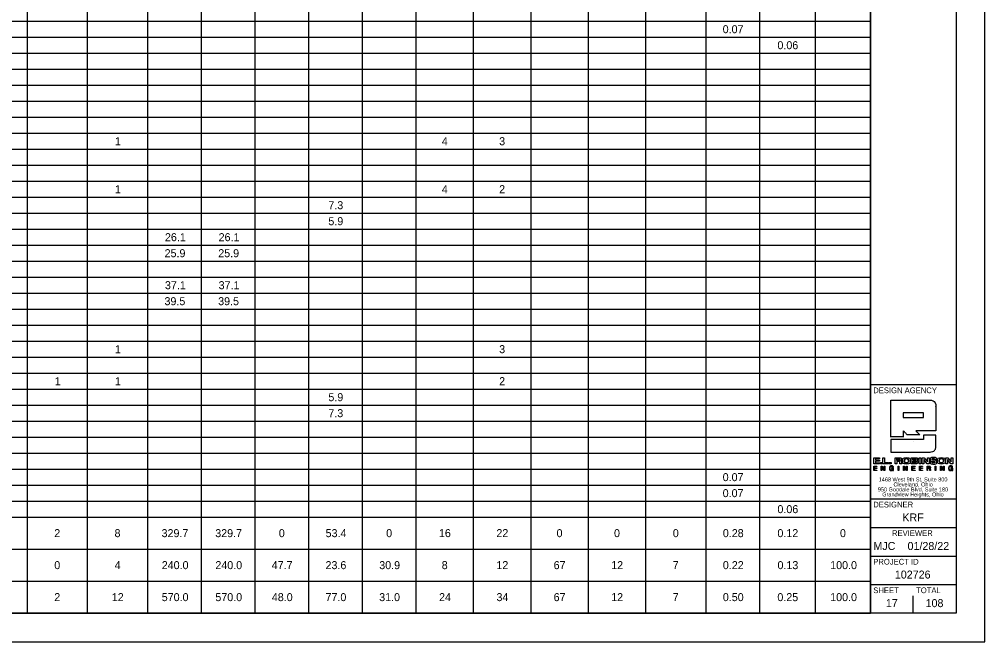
# Model space of a CAD drawing. Extents: x 0 to 34, y 0 to 22.
# Drawn here: x 17.11 to 34, y 0 to 10.89 of the extents above; entities that cross this region are included whole.
import ezdxf

# ---------------------------------------------------------------- set-up
doc = ezdxf.new("R2010")
doc.units = 0
for name, color, linetype in [('SH_Border', 7, 'Continuous'), ('SH_Cut_Line', 7, 'Continuous'), ('SH_Data', 7, 'Continuous'), ('SH_Text', 7, 'Continuous')]:
    doc.layers.add(name, color=color, linetype=linetype)

msp = doc.modelspace()

# ---------------------------------------------------------------- linework, layer by layer
at = {"layer": 'SH_Border'}
for p, q in [((32, 0.5), (32, 21.5)), ((32, 4.5), (33.5, 4.5)), ((32, 2.5), (33.5, 2.5)), ((32, 2), (33.5, 2)), ((32, 1.5), (33.5, 1.5)), ((32, 1), (33.5, 1))]:
    msp.add_line(p, q, dxfattribs=at)
msp.add_lwpolyline([(1.5, 21.5), (33.5, 21.5), (33.5, 0.5), (1.5, 0.5)], close=True, dxfattribs=at)
at = {"layer": 'SH_Cut_Line'}
msp.add_lwpolyline([(0, 0), (34, 0), (34, 22), (0, 22)], close=True, dxfattribs=at)
at = {"layer": 'SH_Data'}
for p, q in [((17.246, 21.5), (17.246, 0.5)), ((18.3, 21.5), (18.3, 0.5)), ((19.354, 21.5), (19.354, 0.5)), ((20.293, 21.5), (20.293, 0.5)), ((21.232, 21.5), (21.232, 0.5)), ((22.171, 21.5), (22.171, 0.5)), ((23.109, 21.5), (23.109, 0.5)), ((24.048, 21.5), (24.048, 0.5)), ((25.053, 21.5), (25.053, 0.5)), ((26.058, 21.5), (26.058, 0.5)), ((27.062, 21.5), (27.062, 0.5)), ((28.067, 21.5), (28.067, 0.5)), ((29.121, 21.5), (29.121, 0.5)), ((30.06, 21.5), (30.06, 0.5)), ((31.032, 21.5), (31.032, 0.5)), ((32.004, 21.5), (32.004, 0.5)), ((1.5, 10.86), (32.004, 10.86)), ((1.5, 10.58), (32.004, 10.58)), ((1.5, 10.3), (32.004, 10.3)), ((1.5, 10.02), (32.004, 10.02)), ((1.5, 9.74), (32.004, 9.74)), ((1.5, 9.46), (32.004, 9.46)), ((1.5, 9.18), (32.004, 9.18)), ((1.5, 8.9), (32.004, 8.9)), ((1.5, 8.62), (32.004, 8.62)), ((1.5, 8.34), (32.004, 8.34)), ((1.5, 8.06), (32.004, 8.06)), ((1.5, 7.78), (32.004, 7.78)), ((1.5, 7.5), (32.004, 7.5)), ((1.5, 7.22), (32.004, 7.22)), ((1.5, 6.94), (32.004, 6.94)), ((1.5, 6.66), (32.004, 6.66)), ((1.5, 6.38), (32.004, 6.38)), ((1.5, 6.1), (32.004, 6.1)), ((1.5, 5.82), (32.004, 5.82)), ((1.5, 5.54), (32.004, 5.54)), ((1.5, 5.26), (32.004, 5.26)), ((1.5, 4.98), (32.004, 4.98)), ((1.5, 4.7), (32.004, 4.7)), ((1.5, 4.42), (32.004, 4.42)), ((1.5, 4.14), (32.004, 4.14)), ((32.929, 4.003), (32.574, 4.003)), ((32.574, 4.003), (32.574, 3.925)), ((32.574, 3.925), (32.929, 3.925)), ((32.929, 3.925), (32.929, 4.003)), ((1.5, 3.86), (32.004, 3.86)), ((1.5, 3.58), (32.004, 3.58)), ((32.75, 3.5), (32.75, 3.5)), ((1.5, 3.3), (32.004, 3.3)), ((32.463, 3.201), (32.463, 3.173)), ((32.743, 3.202), (32.743, 3.178)), ((32.743, 3.159), (32.743, 3.133)), ((33.001, 3.066), (33.001, 3.039)), ((1.5, 3.02), (32.004, 3.02)), ((33.001, 3.039), (33.023, 3.039)), ((1.5, 2.74), (32.004, 2.74)), ((1.5, 2.46), (32.004, 2.46)), ((1.5, 2.18), (32.004, 2.18)), ((1.5, 1.62), (32.004, 1.62)), ((1.5, 1.06), (32.004, 1.06)), ((32.75, 0.5), (32.75, 0.8)), ((32.375, 0.675), (32.375, 0.675)), ((1.5, 0.5), (32.004, 0.5))]:
    msp.add_line(p, q, dxfattribs=at)
for points in [[(32.06, 3.221), (32.161, 3.221), (32.161, 3.201), (32.089, 3.201), (32.089, 3.178), (32.158, 3.178), (32.158, 3.158), (32.089, 3.158), (32.089, 3.133), (32.162, 3.133), (32.162, 3.113), (32.06, 3.113), (32.06, 3.221)], [(32.22, 3.221), (32.249, 3.221), (32.249, 3.134), (32.316, 3.134), (32.316, 3.113), (32.22, 3.113), (32.22, 3.221)], [(32.851, 3.221), (32.881, 3.221), (32.881, 3.113), (32.851, 3.113), (32.851, 3.221)], [(32.999, 3.221), (33.027, 3.221), (33.027, 3.113), (32.995, 3.113), (32.936, 3.189), (32.936, 3.189), (32.936, 3.113), (32.907, 3.113), (32.907, 3.221), (32.941, 3.221), (32.999, 3.146), (32.999, 3.146), (32.999, 3.221)], [(33.413, 3.221), (33.442, 3.221), (33.442, 3.113), (33.41, 3.113), (33.35, 3.189), (33.35, 3.189), (33.35, 3.113), (33.321, 3.113), (33.321, 3.221), (33.356, 3.221), (33.413, 3.146), (33.413, 3.146), (33.413, 3.221)], [(32.059, 3.075), (32.114, 3.075), (32.114, 3.066), (32.07, 3.066), (32.07, 3.041), (32.111, 3.041), (32.111, 3.032), (32.07, 3.032), (32.07, 3.005), (32.114, 3.005), (32.114, 2.996), (32.059, 2.996), (32.059, 3.075)], [(32.175, 3.139), (32.205, 3.139), (32.205, 3.113), (32.175, 3.113), (32.175, 3.139)], [(32.191, 3.075), (32.203, 3.075), (32.244, 3.011), (32.244, 3.011), (32.244, 3.075), (32.254, 3.075), (32.254, 2.996), (32.243, 2.996), (32.202, 3.059), (32.201, 3.059), (32.201, 2.996), (32.191, 2.996), (32.191, 3.075)], [(32.331, 3.139), (32.361, 3.139), (32.361, 3.113), (32.331, 3.113), (32.331, 3.139)], [(32.487, 3.075), (32.498, 3.075), (32.498, 2.996), (32.487, 2.996), (32.487, 3.075)], [(32.581, 3.075), (32.592, 3.075), (32.633, 3.011), (32.633, 3.011), (32.633, 3.075), (32.643, 3.075), (32.643, 2.996), (32.632, 2.996), (32.591, 3.059), (32.591, 3.059), (32.591, 2.996), (32.581, 2.996), (32.581, 3.075)], [(32.726, 3.075), (32.781, 3.075), (32.781, 3.066), (32.737, 3.066), (32.737, 3.041), (32.778, 3.041), (32.778, 3.032), (32.737, 3.032), (32.737, 3.005), (32.781, 3.005), (32.781, 2.996), (32.726, 2.996), (32.726, 3.075)], [(32.859, 3.075), (32.913, 3.075), (32.913, 3.066), (32.869, 3.066), (32.869, 3.041), (32.91, 3.041), (32.91, 3.032), (32.869, 3.032), (32.869, 3.005), (32.913, 3.005), (32.913, 2.996), (32.859, 2.996), (32.859, 3.075)], [(33.133, 3.075), (33.143, 3.075), (33.143, 2.996), (33.133, 2.996), (33.133, 3.075)], [(33.226, 3.075), (33.237, 3.075), (33.279, 3.011), (33.279, 3.011), (33.279, 3.075), (33.289, 3.075), (33.289, 2.996), (33.277, 2.996), (33.236, 3.059), (33.236, 3.059), (33.236, 2.996), (33.226, 2.996), (33.226, 3.075)]]:
    msp.add_lwpolyline(points, dxfattribs=at)
for points, degree in [([(32.356, 3.583), (32.356, 3.586), (32.356, 4.224), (32.356, 4.227)], 2), ([(32.356, 4.227), (32.36, 4.227), (33.03, 4.227), (33.034, 4.227), (33.096, 4.227), (33.147, 4.177), (33.147, 4.114)], 3), ([(33.147, 4.114), (33.147, 4.112), (33.147, 3.694), (33.147, 3.692)], 2), ([(32.929, 3.615), (32.929, 3.615), (33.147, 3.615), (33.147, 3.615), (33.147, 3.615), (33.147, 3.433), (33.147, 3.433), (33.147, 3.37), (33.096, 3.32), (33.034, 3.32), (33.034, 3.32), (32.356, 3.32), (32.356, 3.32), (32.356, 3.32), (32.356, 3.537), (32.356, 3.537), (32.356, 3.537), (32.929, 3.537), (32.929, 3.537), (32.929, 3.537), (32.929, 3.615), (32.929, 3.615)], 3), ([(32.574, 3.583), (32.573, 3.583), (32.357, 3.583), (32.356, 3.583)], 2), ([(32.645, 3.621), (32.645, 3.621), (32.574, 3.691), (32.574, 3.692)], 2), ([(32.574, 3.692), (32.574, 3.691), (32.574, 3.583), (32.574, 3.583)], 2), ([(32.866, 3.621), (32.865, 3.621), (32.646, 3.621), (32.645, 3.621)], 2), ([(33.147, 3.692), (33.145, 3.692), (32.795, 3.692), (32.793, 3.692)], 2), ([(32.793, 3.692), (32.793, 3.691), (32.866, 3.621), (32.866, 3.621)], 2), ([(32.433, 3.113), (32.433, 3.113), (32.433, 3.221), (32.433, 3.221)], 2), ([(32.433, 3.221), (32.433, 3.221), (32.512, 3.221), (32.512, 3.221), (32.542, 3.221), (32.545, 3.203), (32.546, 3.192)], 3), ([(32.631, 3.11), (32.573, 3.11), (32.567, 3.145), (32.565, 3.167), (32.564, 3.19), (32.573, 3.224), (32.631, 3.224)], 3), ([(32.631, 3.224), (32.69, 3.224), (32.695, 3.189), (32.697, 3.167), (32.699, 3.144), (32.69, 3.11), (32.631, 3.11)], 3), ([(32.714, 3.113), (32.714, 3.113), (32.714, 3.221), (32.714, 3.221)], 2), ([(32.714, 3.221), (32.714, 3.221), (32.795, 3.221), (32.795, 3.221)], 2), ([(32.795, 3.221), (32.81, 3.218), (32.826, 3.214), (32.826, 3.194)], 2), ([(33.126, 3.19), (33.124, 3.204), (33.111, 3.206), (33.099, 3.206), (33.087, 3.206), (33.079, 3.2), (33.079, 3.193), (33.079, 3.187), (33.084, 3.184), (33.091, 3.183), (33.091, 3.183), (33.128, 3.177), (33.128, 3.177), (33.148, 3.173), (33.163, 3.166), (33.163, 3.146), (33.163, 3.126), (33.149, 3.11), (33.107, 3.11), (33.08, 3.11), (33.046, 3.113), (33.045, 3.147), (33.045, 3.147), (33.079, 3.147), (33.079, 3.147), (33.079, 3.132), (33.094, 3.129), (33.107, 3.129), (33.121, 3.129), (33.13, 3.134), (33.13, 3.143), (33.13, 3.151), (33.123, 3.154), (33.112, 3.155), (33.112, 3.155), (33.085, 3.16), (33.085, 3.16), (33.066, 3.162), (33.047, 3.168), (33.047, 3.19), (33.047, 3.215), (33.067, 3.224), (33.101, 3.224), (33.124, 3.224), (33.157, 3.221), (33.159, 3.19), (33.159, 3.19), (33.126, 3.19), (33.126, 3.19)], 3), ([(33.242, 3.11), (33.183, 3.11), (33.178, 3.145), (33.176, 3.167), (33.174, 3.19), (33.183, 3.224), (33.242, 3.224)], 3), ([(33.242, 3.224), (33.3, 3.224), (33.306, 3.189), (33.308, 3.167), (33.309, 3.144), (33.3, 3.11), (33.242, 3.11)], 3), ([(32.396, 3.006), (32.39, 2.998), (32.38, 2.994), (32.37, 2.994), (32.347, 2.994), (32.333, 3.014), (32.333, 3.034), (32.333, 3.057), (32.346, 3.077), (32.37, 3.077), (32.388, 3.077), (32.401, 3.069), (32.404, 3.051), (32.404, 3.051), (32.394, 3.051), (32.394, 3.051), (32.392, 3.062), (32.382, 3.068), (32.37, 3.068), (32.351, 3.068), (32.344, 3.051), (32.344, 3.034), (32.344, 3.018), (32.353, 3.003), (32.37, 3.003), (32.387, 3.003), (32.396, 3.015), (32.396, 3.029), (32.396, 3.029), (32.371, 3.029), (32.371, 3.029), (32.371, 3.029), (32.371, 3.038), (32.371, 3.038), (32.371, 3.038), (32.405, 3.038), (32.405, 3.038), (32.405, 3.038), (32.405, 2.996), (32.405, 2.996), (32.405, 2.996), (32.398, 2.996), (32.398, 2.996), (32.398, 2.996), (32.396, 3.006), (32.396, 3.006)], 3), ([(32.463, 3.113), (32.462, 3.113), (32.433, 3.113), (32.433, 3.113)], 2), ([(32.499, 3.153), (32.499, 3.153), (32.463, 3.153), (32.463, 3.153)], 2), ([(32.463, 3.173), (32.463, 3.173), (32.502, 3.173), (32.502, 3.173), (32.508, 3.173), (32.516, 3.177), (32.516, 3.187), (32.516, 3.198), (32.507, 3.201), (32.5, 3.201), (32.5, 3.201), (32.463, 3.201), (32.463, 3.201), (32.463, 3.201), (32.463, 3.173), (32.463, 3.173)], 3), ([(32.463, 3.173), (32.476, 3.173), (32.489, 3.173), (32.508, 3.173), (32.516, 3.177), (32.516, 3.198), (32.507, 3.201), (32.488, 3.201), (32.475, 3.201), (32.463, 3.201)], 3), ([(32.463, 3.153), (32.463, 3.152), (32.463, 3.113), (32.463, 3.113)], 2), ([(32.518, 3.113), (32.516, 3.118), (32.516, 3.122), (32.516, 3.134), (32.515, 3.149), (32.508, 3.15), (32.499, 3.153)], 3), ([(32.55, 3.113), (32.55, 3.113), (32.518, 3.113), (32.518, 3.113)], 2), ([(32.546, 3.192), (32.544, 3.179), (32.542, 3.17), (32.53, 3.166)], 2), ([(32.53, 3.166), (32.53, 3.166), (32.53, 3.165), (32.53, 3.165)], 2), ([(32.53, 3.165), (32.543, 3.163), (32.544, 3.147), (32.544, 3.136)], 2), ([(32.544, 3.136), (32.544, 3.131), (32.548, 3.119), (32.55, 3.113)], 2), ([(32.631, 3.13), (32.658, 3.13), (32.667, 3.15), (32.667, 3.167), (32.667, 3.184), (32.658, 3.204), (32.631, 3.204), (32.604, 3.204), (32.595, 3.184), (32.595, 3.167), (32.595, 3.15), (32.604, 3.13), (32.631, 3.13)], 3), ([(32.631, 3.204), (32.604, 3.204), (32.595, 3.184), (32.595, 3.167), (32.595, 3.15), (32.604, 3.13), (32.631, 3.13)], 3), ([(32.631, 3.13), (32.658, 3.13), (32.667, 3.15), (32.667, 3.167), (32.667, 3.184), (32.658, 3.204), (32.631, 3.204)], 3), ([(32.829, 3.145), (32.827, 3.132), (32.824, 3.113), (32.791, 3.113), (32.791, 3.113), (32.714, 3.113), (32.714, 3.113)], 3), ([(32.743, 3.178), (32.743, 3.178), (32.784, 3.178), (32.784, 3.178), (32.791, 3.178), (32.796, 3.182), (32.796, 3.19), (32.796, 3.197), (32.793, 3.202), (32.78, 3.202), (32.78, 3.202), (32.743, 3.202), (32.743, 3.202), (32.743, 3.202), (32.743, 3.178), (32.743, 3.178)], 3), ([(32.743, 3.178), (32.757, 3.178), (32.771, 3.178), (32.791, 3.181), (32.791, 3.183), (32.792, 3.197), (32.793, 3.202), (32.768, 3.202), (32.756, 3.202), (32.743, 3.202)], 3), ([(32.743, 3.133), (32.743, 3.133), (32.787, 3.133), (32.787, 3.133), (32.796, 3.133), (32.8, 3.139), (32.8, 3.146), (32.8, 3.155), (32.794, 3.159), (32.784, 3.159), (32.784, 3.159), (32.743, 3.159), (32.743, 3.159), (32.743, 3.159), (32.743, 3.133), (32.743, 3.133)], 3), ([(32.743, 3.133), (32.758, 3.133), (32.772, 3.133), (32.796, 3.133), (32.8, 3.139), (32.8, 3.155), (32.794, 3.159), (32.77, 3.159), (32.757, 3.159), (32.743, 3.159)], 3), ([(32.826, 3.194), (32.824, 3.186), (32.822, 3.175), (32.812, 3.172)], 2), ([(32.812, 3.172), (32.812, 3.172), (32.812, 3.172), (32.812, 3.172)], 2), ([(32.812, 3.172), (32.824, 3.17), (32.827, 3.156), (32.829, 3.145)], 2), ([(32.991, 3.075), (32.991, 3.075), (33.027, 3.075), (33.028, 3.075), (33.042, 3.075), (33.051, 3.067), (33.051, 3.054)], 3), ([(32.991, 2.996), (32.991, 2.997), (32.991, 3.074), (32.991, 3.075)], 2), ([(33.023, 3.039), (33.033, 3.039), (33.041, 3.041), (33.041, 3.052), (33.041, 3.06), (33.037, 3.066), (33.027, 3.066), (33.027, 3.066), (33.001, 3.066), (33.001, 3.066), (33.001, 3.066), (33.001, 3.039), (33.001, 3.039), (33.001, 3.039), (33.023, 3.039), (33.023, 3.039)], 3), ([(33.023, 3.039), (33.033, 3.039), (33.041, 3.041), (33.041, 3.06), (33.037, 3.066), (33.018, 3.066), (33.01, 3.066), (33.001, 3.066)], 3), ([(33.051, 3.054), (33.049, 3.045), (33.047, 3.037), (33.038, 3.034)], 2), ([(33.242, 3.13), (33.269, 3.13), (33.278, 3.15), (33.278, 3.167), (33.278, 3.184), (33.269, 3.204), (33.242, 3.204), (33.215, 3.204), (33.205, 3.184), (33.205, 3.167), (33.205, 3.15), (33.215, 3.13), (33.242, 3.13)], 3), ([(33.242, 3.204), (33.215, 3.204), (33.205, 3.184), (33.205, 3.167), (33.205, 3.15), (33.215, 3.13), (33.242, 3.13)], 3), ([(33.242, 3.13), (33.269, 3.13), (33.278, 3.15), (33.278, 3.167), (33.278, 3.184), (33.269, 3.204), (33.242, 3.204)], 3), ([(33.43, 3.006), (33.424, 2.998), (33.414, 2.994), (33.405, 2.994), (33.382, 2.994), (33.368, 3.014), (33.368, 3.034), (33.368, 3.057), (33.38, 3.077), (33.405, 3.077), (33.422, 3.077), (33.436, 3.069), (33.439, 3.051), (33.439, 3.051), (33.429, 3.051), (33.429, 3.051), (33.426, 3.062), (33.417, 3.068), (33.405, 3.068), (33.386, 3.068), (33.378, 3.051), (33.378, 3.034), (33.378, 3.018), (33.388, 3.003), (33.405, 3.003), (33.421, 3.003), (33.431, 3.015), (33.43, 3.029), (33.43, 3.029), (33.405, 3.029), (33.405, 3.029), (33.405, 3.029), (33.405, 3.038), (33.405, 3.038), (33.405, 3.038), (33.44, 3.038), (33.44, 3.038), (33.44, 3.038), (33.44, 2.996), (33.44, 2.996), (33.44, 2.996), (33.433, 2.996), (33.433, 2.996), (33.433, 2.996), (33.43, 3.006), (33.43, 3.006)], 3), ([(33.001, 2.996), (33.001, 2.996), (32.991, 2.996), (32.991, 2.996)], 2), ([(33.04, 3.016), (33.038, 3.023), (33.037, 3.03), (33.027, 3.03), (33.027, 3.03), (33.001, 3.03), (33.001, 3.03)], 3), ([(33.001, 3.03), (33.001, 3.03), (33.001, 2.996), (33.001, 2.996)], 2), ([(33.038, 3.034), (33.038, 3.034), (33.038, 3.034), (33.038, 3.034)], 2), ([(33.038, 3.034), (33.044, 3.029), (33.047, 3.025), (33.048, 3.018)], 2), ([(33.043, 2.996), (33.042, 3), (33.041, 3.008), (33.04, 3.016)], 2), ([(33.054, 2.996), (33.054, 2.996), (33.043, 2.996), (33.043, 2.996)], 2), ([(33.048, 3.018), (33.049, 3.01), (33.052, 3.002), (33.054, 2.996)], 2)]:
    msp.add_open_spline(points, degree=degree, dxfattribs=at)

# ---------------------------------------------------------------- texts
for s, height, p in [('DESIGN AGENCY', 0.1, (32.05, 4.35)), ('1468 West 9th St, Suite 800', 0.07, (32.145, 2.805)), ('950 Goodale Blvd, Suite 180', 0.07, (32.13, 2.63)), ('Cleveland, Ohio', 0.07, (32.404, 2.717)), ('Grandview Heights, Ohio', 0.07, (32.208, 2.542)), ('DESIGNER', 0.1, (32.05, 2.35)), ('KRF', 0.14, (32.559, 2.105)), ('REVIEWER', 0.1, (32.378, 1.85)), ('MJC', 0.14, (32.053, 1.605)), ('01/28/22', 0.14, (32.65, 1.605)), ('PROJECT ID', 0.1, (32.05, 1.35)), ('102726', 0.14, (32.428, 1.105)), ('SHEET', 0.1, (32.05, 0.85)), ('TOTAL', 0.1, (32.8, 0.85)), ('17', 0.14, (32.271, 0.605)), ('108', 0.14, (32.966, 0.605))]:
    msp.add_text(s, height=height, dxfattribs=at).set_placement(p)
at = {"layer": 'SH_Text'}
for s, p in [('0.07', (29.416, 10.65)), ('0.06', (30.374, 10.37)), ('1', (18.785, 8.69)), ('4', (24.503, 8.69)), ('3', (25.506, 8.69)), ('1', (18.785, 7.85)), ('4', (24.503, 7.85)), ('2', (25.506, 7.85)), ('7.3', (22.518, 7.57)), ('5.9', (22.518, 7.29)), ('26.1', (19.659, 7.01)), ('26.1', (20.598, 7.01)), ('25.9', (19.653, 6.73)), ('25.9', (20.592, 6.73)), ('37.1', (19.659, 6.17)), ('37.1', (20.598, 6.17)), ('39.5', (19.651, 5.89)), ('39.5', (20.59, 5.89)), ('1', (18.785, 5.05)), ('3', (25.506, 5.05)), ('1', (17.731, 4.49)), ('1', (18.785, 4.49)), ('2', (25.506, 4.49)), ('5.9', (22.518, 4.21)), ('7.3', (22.518, 3.93)), ('0.07', (29.416, 2.81)), ('0.07', (29.416, 2.53)), ('0.06', (30.374, 2.25)), ('2', (17.723, 1.83)), ('8', (18.777, 1.83)), ('329.7', (19.6, 1.83)), ('329.7', (20.539, 1.83)), ('0', (21.651, 1.83)), ('53.4', (22.47, 1.83)), ('0', (23.529, 1.83)), ('16', (24.452, 1.83)), ('22', (25.457, 1.83)), ('0', (26.51, 1.83)), ('0', (27.515, 1.83)), ('0', (28.544, 1.83)), ('0.28', (29.419, 1.83)), ('0.12', (30.374, 1.83)), ('0', (31.468, 1.83)), ('0', (17.723, 1.27)), ('4', (18.779, 1.27)), ('240.0', (19.603, 1.27)), ('240.0', (20.541, 1.27)), ('47.7', (21.527, 1.27)), ('23.6', (22.468, 1.27)), ('30.9', (23.408, 1.27)), ('8', (24.501, 1.27)), ('12', (25.457, 1.27)), ('67', (26.459, 1.27)), ('12', (27.466, 1.27)), ('7', (28.542, 1.27)), ('0.22', (29.419, 1.27)), ('0.13', (30.375, 1.27)), ('100.0', (31.297, 1.27)), ('2', (17.723, 0.71)), ('12', (18.729, 0.71)), ('570.0', (19.603, 0.71)), ('570.0', (20.541, 0.71)), ('48.0', (21.529, 0.71)), ('77.0', (22.468, 0.71)), ('31.0', (23.407, 0.71)), ('24', (24.454, 0.71)), ('34', (25.459, 0.71)), ('67', (26.459, 0.71)), ('12', (27.466, 0.71)), ('7', (28.542, 0.71)), ('0.50', (29.419, 0.71)), ('0.25', (30.373, 0.71)), ('100.0', (31.297, 0.71))]:
    msp.add_text(s, height=0.14, dxfattribs=at).set_placement(p)

doc.saveas('drawing.dxf')
